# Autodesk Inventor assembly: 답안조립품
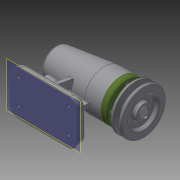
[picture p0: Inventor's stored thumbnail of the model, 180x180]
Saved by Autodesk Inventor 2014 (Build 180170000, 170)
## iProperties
Created: 2017-01
Part Number: 답안조립품
Document SubType Name: Assembly
Designer: owner
Author: owner
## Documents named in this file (12)
- C:\Users\owner\Desktop\470107V1001\답안조립품.iam
- C:\Users\owner\Desktop\470107V1001\1본체.ipt
- C:\Users\owner\Desktop\470107V1001\축.ipt
- C:\Users\owner\Desktop\470107V1001\베어링 6004.ipt
- C:\Users\owner\Desktop\470107V1001\어댑터슬리브.ipt
- C:\Users\owner\Desktop\470107V1001\볼트 M4 x 12.ipt
- C:\Users\owner\Desktop\470107V1001\베어링 51202.ipt
- C:\Users\owner\Desktop\470107V1001\커버.ipt
- C:\Users\owner\Desktop\470107V1001\오일 실.ipt
- C:\Users\owner\Desktop\470107V1001\키 5 x 5 x 16.ipt
- C:\Users\owner\Desktop\470107V1001\V벨트풀리.ipt
- C:\Users\owner\Desktop\470107V1001\멈춤나사 M3x8.ipt
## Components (7 placed, 3 different names)
1. 1본체:1
2. ISO 4762 M4 x 12:1 — 각도:1, 각도:2
3. V벨트풀리:1 — 각도:4
4. ISO 4762 M4 x 12:2
5. ISO 4762 M4 x 12:3
6. ISO 4762 M4 x 12:4
7. ISO 4762 M4 x 12:5
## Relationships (3: Angle 3)
- 각도:1 [Angle]: ISO 4762 M4 x 12:1
- 각도:2 [Angle]: ISO 4762 M4 x 12:1
- 각도:4 [Angle]: V벨트풀리:1
